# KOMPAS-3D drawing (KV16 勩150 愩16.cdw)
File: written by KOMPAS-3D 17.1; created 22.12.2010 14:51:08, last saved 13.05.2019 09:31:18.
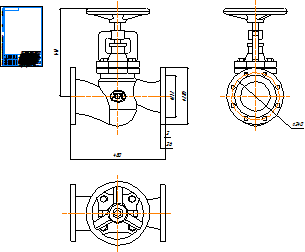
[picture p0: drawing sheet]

Title block, sheet 1: name: KV16 Ду150 Ру16; material: Внимание! Данный продукт является объектом авторского права ООО «Торговый Дом АДЛ». / Запрещается изменение, копирование, распространение / (в том числе путем копирования на другие сайты и ресурсы в Интернете) / или любое иное использование информации и объектов без предварительного / согласия правообладателя (ООО «Торговый Дом АДЛ»).; scale: 1:1; sheets: 1; organisation: ООО "Торговый дом АДЛ"; sheet format: A4; stored path: \\adlc.lan\data\АДЛ_ПКД\3D-модели\ADL production\Вентили ГРАНВЕНТ\KV16\KOMPAS 2D\KV16 Ду150 Ру16.cdw

Views: Спереди 1, Проекционный вид 2, Проекционный вид 3
Dimensions and other numbers on the sheet: 212; 285; 480; 2; 26; 240; 441; 1:1; 1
